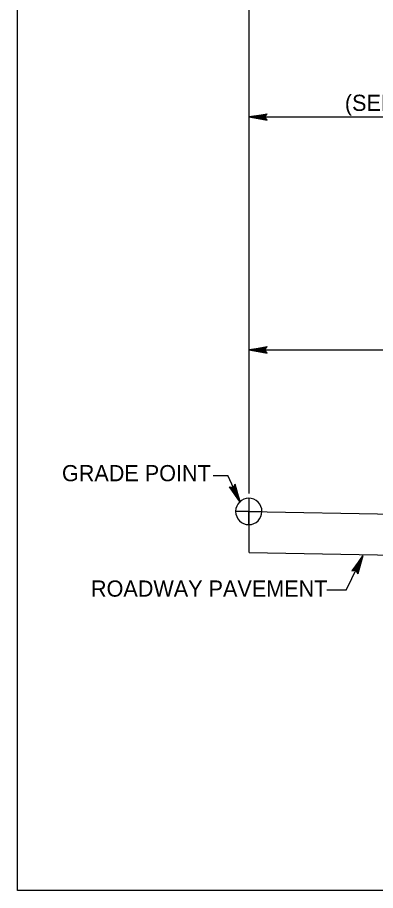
# Model space of a CAD drawing. Extents: x 1553195 to 1553792, y 810516 to 810787.
# Drawn here: x 1553739.44 to 1553751.08, y 810694.82 to 810723.14 of the extents above; entities that cross this region are included whole.
import ezdxf

# ---------------------------------------------------------------- set-up
doc = ezdxf.new("R2010")
doc.units = 0
doc.layers.add('Old_Level_28', color=7, linetype='Continuous')

msp = doc.modelspace()

# ---------------------------------------------------------------- linework, layer by layer
at = {"layer": 'Old_Level_28'}
for p, q in [((1553746.957, 810727.211), (1553746.957, 810707.692)), ((1553746.957, 810719.917), (1553747.552, 810720.019)), ((1553746.957, 810719.917), (1553747.539, 810720.004)), ((1553747.53, 810719.99), (1553746.957, 810719.917)), ((1553746.957, 810719.917), (1553747.519, 810719.975)), ((1553747.508, 810719.96), (1553746.957, 810719.917)), ((1553746.957, 810719.917), (1553747.497, 810719.946)), ((1553747.477, 810719.917), (1553747.552, 810720.019)), ((1553747.486, 810719.931), (1553746.957, 810719.917)), ((1553746.957, 810719.917), (1553766.737, 810719.917)), ((1553746.957, 810719.917), (1553747.552, 810719.81)), ((1553747.539, 810719.826), (1553746.957, 810719.917)), ((1553746.957, 810719.917), (1553747.53, 810719.84)), ((1553747.519, 810719.855), (1553746.957, 810719.917)), ((1553746.957, 810719.917), (1553747.508, 810719.871)), ((1553747.497, 810719.884), (1553746.957, 810719.917)), ((1553746.957, 810719.917), (1553747.486, 810719.899)), ((1553747.477, 810719.917), (1553746.957, 810719.917)), ((1553747.552, 810719.81), (1553747.477, 810719.917)), ((1553746.957, 810712.359), (1553747.552, 810712.461)), ((1553746.957, 810712.359), (1553747.539, 810712.445)), ((1553747.53, 810712.432), (1553746.957, 810712.359)), ((1553746.957, 810712.359), (1553747.519, 810712.417)), ((1553747.508, 810712.402), (1553746.957, 810712.359)), ((1553746.957, 810712.359), (1553747.497, 810712.388)), ((1553747.486, 810712.372), (1553746.957, 810712.359)), ((1553746.957, 810712.359), (1553752.957, 810712.359)), ((1553746.957, 810712.359), (1553747.552, 810712.252)), ((1553747.539, 810712.268), (1553746.957, 810712.359)), ((1553746.957, 810712.359), (1553747.53, 810712.281)), ((1553747.519, 810712.297), (1553746.957, 810712.359)), ((1553746.957, 810712.359), (1553747.508, 810712.312)), ((1553747.497, 810712.326), (1553746.957, 810712.359)), ((1553746.957, 810712.359), (1553747.486, 810712.341)), ((1553747.477, 810712.359), (1553746.957, 810712.359)), ((1553747.477, 810712.359), (1553747.552, 810712.461)), ((1553747.552, 810712.252), (1553747.477, 810712.359)), ((1553745.798, 810708.277), (1553746.271, 810708.277)), ((1553746.682, 810707.421), (1553746.271, 810708.277)), ((1553746.682, 810707.421), (1553746.327, 810707.912)), ((1553746.327, 810707.912), (1553746.458, 810707.888)), ((1553746.347, 810707.91), (1553746.682, 810707.421)), ((1553746.682, 810707.421), (1553746.365, 810707.907)), ((1553746.382, 810707.901), (1553746.682, 810707.421)), ((1553746.682, 810707.421), (1553746.402, 810707.899)), ((1553746.42, 810707.897), (1553746.682, 810707.421)), ((1553746.682, 810707.421), (1553746.44, 810707.894)), ((1553746.458, 810707.888), (1553746.515, 810708.003)), ((1553746.458, 810707.888), (1553746.682, 810707.421)), ((1553746.467, 810707.906), (1553746.682, 810707.421)), ((1553746.682, 810707.421), (1553746.473, 810707.921)), ((1553746.482, 810707.939), (1553746.682, 810707.421)), ((1553746.682, 810707.421), (1553746.493, 810707.955)), ((1553746.5, 810707.972), (1553746.682, 810707.421)), ((1553746.682, 810707.421), (1553746.509, 810707.988)), ((1553746.682, 810707.421), (1553746.515, 810708.003)), ((1553746.957, 810707.542), (1553746.957, 810707.115)), ((1553746.957, 810707.115), (1553746.53, 810707.112)), ((1553746.957, 810707.115), (1553752.95, 810707.004)), ((1553746.957, 810707.115), (1553746.957, 810707.115)), ((1553746.957, 810706.688), (1553746.957, 810707.115)), ((1553746.957, 810707.115), (1553747.383, 810707.115)), ((1553746.968, 810705.786), (1553746.968, 810707.115)), ((1553746.968, 810705.786), (1553752.959, 810705.675)), ((1553750.123, 810704.561), (1553750.663, 810705.679)), ((1553750.663, 810705.679), (1553750.308, 810705.188)), ((1553750.328, 810705.19), (1553750.663, 810705.679)), ((1553750.663, 810705.679), (1553750.346, 810705.193)), ((1553750.363, 810705.199), (1553750.663, 810705.679)), ((1553750.663, 810705.679), (1553750.383, 810705.201)), ((1553750.402, 810705.203), (1553750.663, 810705.679)), ((1553750.663, 810705.679), (1553750.422, 810705.206)), ((1553750.439, 810705.213), (1553750.663, 810705.679)), ((1553750.448, 810705.194), (1553750.663, 810705.679)), ((1553750.663, 810705.679), (1553750.455, 810705.179)), ((1553750.464, 810705.161), (1553750.663, 810705.679)), ((1553750.663, 810705.679), (1553750.475, 810705.145)), ((1553750.481, 810705.128), (1553750.663, 810705.679)), ((1553750.663, 810705.679), (1553750.49, 810705.112)), ((1553750.663, 810705.679), (1553750.497, 810705.096)), ((1553750.308, 810705.188), (1553750.439, 810705.213)), ((1553750.439, 810705.213), (1553750.497, 810705.096)), ((1553750.123, 810704.561), (1553749.49, 810704.561))]:
    msp.add_line(p, q, dxfattribs=at)
msp.add_lwpolyline([(1553739.439, 810764.018), (1553791.973, 810764.018), (1553791.973, 810694.817), (1553739.439, 810694.817)], close=True, dxfattribs=at)
for start, end in [(90.1432, 179.2898), (359.8329, 90.1432), (180.2626, 269.8568), (269.8568, 359.8329)]:
    msp.add_arc((1553746.957, 810707.115), 0.427, start, end, dxfattribs=at)

# ---------------------------------------------------------------- texts
for s, p in [('(SEE ROADWAY TYPICAL SECTION ', (1553750.08, 810720.109)), ('GRADE POINT', (1553740.886, 810708.095)), ('ROADWAY PAVEMENT', (1553741.829, 810704.351))]:
    msp.add_text(s, height=0.52493, dxfattribs=at).set_placement(p)

doc.saveas('drawing.dxf')
